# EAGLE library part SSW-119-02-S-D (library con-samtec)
THROUGH-HOLE .025" SQ POST SOCKET Source: Samtec SSW.pdf
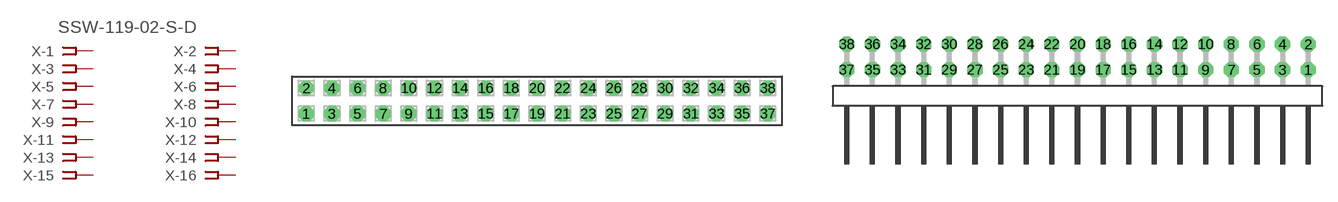
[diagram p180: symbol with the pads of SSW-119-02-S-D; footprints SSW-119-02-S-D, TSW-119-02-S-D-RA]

Designator prefix X; gates -1=FPINV -2=FPIN -3=FPIN -4=FPIN -5=FPIN -6=FPIN -7=FPIN -8=FPIN -9=FPIN -10=FPIN -11=FPIN -12=FPIN -13=FPIN -14=FPIN -15=FPIN -16=FPIN -17=FPIN -18=FPIN -19=FPIN -20=FPIN -21=FPIN -22=FPIN -23=FPIN -24=FPIN -25=FPIN -26=FPIN -27=FPIN -28=FPIN -29=FPIN -30=FPIN -31=FPIN -32=FPIN -33=FPIN -34=FPIN -35=FPIN -36=FPIN -37=FPIN -38=FPIN

## SSW-119-02-S-D (MPN: SSW-119-02-S-D; OC_FARNELL: unknown; OC_NEWARK: 11P9623)  [SSW-119-02-S-D]
1  -1:1  pas
2  -2:1  pas
3  -3:1  pas
4  -4:1  pas
5  -5:1  pas
6  -6:1  pas
7  -7:1  pas
8  -8:1  pas
9  -9:1  pas
10  -10:1  pas
11  -11:1  pas
12  -12:1  pas
13  -13:1  pas
14  -14:1  pas
15  -15:1  pas
16  -16:1  pas
17  -17:1  pas
18  -18:1  pas
19  -19:1  pas
20  -20:1  pas
21  -21:1  pas
22  -22:1  pas
23  -23:1  pas
24  -24:1  pas
25  -25:1  pas
26  -26:1  pas
27  -27:1  pas
28  -28:1  pas
29  -29:1  pas
30  -30:1  pas
31  -31:1  pas
32  -32:1  pas
33  -33:1  pas
34  -34:1  pas
35  -35:1  pas
36  -36:1  pas
37  -37:1  pas
38  -38:1  pas

## SSW-119-02-S-D-RA (MPN: SSW-119-02-S-D-RA; OC_FARNELL: unknown; OC_NEWARK: 11P9624)  [TSW-119-02-S-D-RA]
Pads as for SSW-119-02-S-D

## Footprint SSW-119-02-S-D (pad centres in mm)
THROUGH-HOLE .025" SQ POST SOCKET Source: Samtec SSW.pdf
drill 1 pad 1.5 octagon: 1 -22.86,-1.27; 2 -22.86,1.27; 3 -20.32,-1.27; 4 -20.32,1.27; 5 -17.78,-1.27; 6 -17.78,1.27; 7 -15.24,-1.27; 8 -15.24,1.27; 9 -12.7,-1.27; 10 -12.7,1.27; 11 -10.16,-1.27; 12 -10.16,1.27; 13 -7.62,-1.27; 14 -7.62,1.27; 15 -5.08,-1.27; 16 -5.08,1.27; 17 -2.54,-1.27; 18 -2.54,1.27; 19 0,-1.27; 20 0,1.27; 21 2.54,-1.27; 22 2.54,1.27; 23 5.08,-1.27; 24 5.08,1.27; 25 7.62,-1.27; 26 7.62,1.27; 27 10.16,-1.27; 28 10.16,1.27; 29 12.7,-1.27; 30 12.7,1.27; 31 15.24,-1.27; 32 15.24,1.27; 33 17.78,-1.27; 34 17.78,1.27; 35 20.32,-1.27; 36 20.32,1.27; 37 22.86,-1.27; 38 22.86,1.27

## Footprint TSW-119-02-S-D-RA (pad centres in mm)
THROUGH-HOLE .025" SQ POST HEADER Source: Samtec TSW.pdf
drill 1 pad 1.5 octagon: 1 22.86,1.524; 2 22.86,4.064; 3 20.32,1.524; 4 20.32,4.064; 5 17.78,1.524; 6 17.78,4.064; 7 15.24,1.524; 8 15.24,4.064; 9 12.7,1.524; 10 12.7,4.064; 11 10.16,1.524; 12 10.16,4.064; 13 7.62,1.524; 14 7.62,4.064; 15 5.08,1.524; 16 5.08,4.064; 17 2.54,1.524; 18 2.54,4.064; 19 0,1.524; 20 0,4.064; 21 -2.54,1.524; 22 -2.54,4.064; 23 -5.08,1.524; 24 -5.08,4.064; 25 -7.62,1.524; 26 -7.62,4.064; 27 -10.16,1.524; 28 -10.16,4.064; 29 -12.7,1.524; 30 -12.7,4.064; 31 -15.24,1.524; 32 -15.24,4.064; 33 -17.78,1.524; 34 -17.78,4.064; 35 -20.32,1.524; 36 -20.32,4.064; 37 -22.86,1.524; 38 -22.86,4.064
